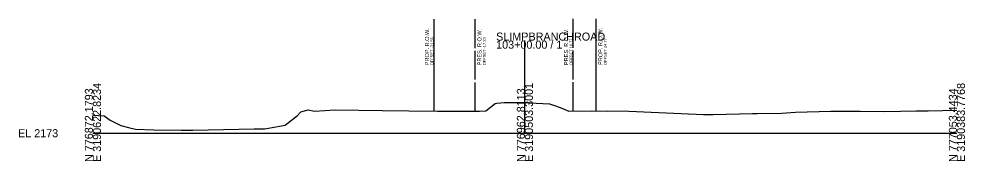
# Model space of a CAD drawing. Extents: x -26 to 303, y -10 to 13517.
# Drawn here: x -25.7 to 302.8, y -9.7 to 39.7 of the extents above; entities that cross this region are included whole.
import ezdxf

# ---------------------------------------------------------------- set-up
doc = ezdxf.new("R2010")
doc.units = 0
for name, color, linetype in [('DESIGN - ROW - Right-of-Way and Easement Labels', 7, 'Continuous'), ('DESIGN - ROW - Right-of-Way Linework', 7, 'Continuous'), ('DESIGN - SHEET - Light Grid', 7, 'Continuous'), ('SURVEY - GROUND - Top of Ground', 7, 'Continuous'), ('SURVEY - PROPERTY - ROW Lines', 7, 'Continuous'), ('SURVEY - PROPERTY - ROW Lines Text', 7, 'Continuous')]:
    doc.layers.add(name, color=color, linetype=linetype)

msp = doc.modelspace()

# ---------------------------------------------------------------- linework, layer by layer
at = {"layer": 'DESIGN - ROW - Right-of-Way Linework'}
for p, q in [((118.45, 7.63), (118.45, 39.63)), ((174.77, 7.74), (174.77, 39.74))]:
    msp.add_line(p, q, dxfattribs=at)
at = {"layer": 'DESIGN - SHEET - Light Grid'}
for p, q in [((150, 0), (150, 32.19)), ((0, 0), (150, 0)), ((150, 0), (300, 0))]:
    msp.add_line(p, q, dxfattribs=at)
at = {"layer": 'SURVEY - GROUND - Top of Ground'}
msp.add_lwpolyline([(0, 6.29), (3.95, 6.04), (5.99, 4.56), (9.72, 2.63), (12.36, 1.95), (14.77, 1.38), (21.19, 1.16), (30.66, 1.03), (31.22, 1.04), (34.66, 1.11), (55.95, 1.52), (59.69, 1.57), (61.57, 1.89), (66.72, 2.83), (67.92, 3.75), (68.99, 4.53), (70.87, 6.06), (72.22, 7.47), (74.77, 8.13), (76.91, 7.66), (84.14, 8.16), (100.42, 7.89), (109.68, 7.75), (119.63, 7.61), (123.9, 7.7), (134.27, 7.61), (136.49, 7.81), (139.66, 10.36), (140.23, 10.41), (142.81, 10.73), (143.32, 10.73), (149.93, 10.67), (151.56, 10.58), (158.49, 10.23), (160.67, 9.57), (162.81, 8.68), (165.3, 7.7), (173.22, 7.79), (178.51, 7.65), (183.5, 7.73), (211.99, 6.47), (215.34, 6.54), (229.02, 6.84), (230.66, 6.84), (239.2, 6.93), (243.9, 7.33), (256.18, 7.7), (266.4, 7.62), (275.01, 7.6), (285.86, 7.74), (290.07, 7.75), (300, 8.03)], dxfattribs=at)
at = {"layer": 'SURVEY - PROPERTY - ROW Lines'}
for p, q in [((132.77, 29.62), (132.77, 39.62)), ((166.77, 29.71), (166.77, 39.71)), ((132.77, 18.62), (132.77, 28.62)), ((166.77, 18.71), (166.77, 28.71)), ((132.77, 7.62), (132.77, 17.62)), ((166.77, 7.71), (166.77, 17.71))]:
    msp.add_line(p, q, dxfattribs=at)

# ---------------------------------------------------------------- texts
at = {"layer": 'DESIGN - ROW - Right-of-Way and Easement Labels'}
for s, height, p in [('PROP. R.O.W.', 1.4, (116.7, 23.63)), ('OFFSET -31.55', 1, (118.2, 23.63)), ('PROP. R.O.W.', 1.4, (176.92, 23.74)), ('OFFSET 24.77', 1, (178.42, 23.74))]:
    msp.add_text(s, height=height, rotation=90, dxfattribs=at).set_placement(p)
at = {"layer": 'DESIGN - SHEET - Light Grid'}
for s, p in [('SLIMPBRANCHROAD', (140, 32.19)), ('103+00.00 / 1', (140, 29.39)), ('EL 2173', (-26, -1.4))]:
    msp.add_text(s, height=2.8, dxfattribs=at).set_placement(p)
for s, p in [('E 3190622.8234', (2.8, -10)), ('E 3190503.3001', (152.8, -10)), ('E 3190383.7768', (302.8, -10)), ('N 776872.1793', (0, -10)), ('N 776962.8113', (150, -10)), ('N 777053.4434', (300, -10))]:
    msp.add_text(s, height=2.8, rotation=90, dxfattribs=at).set_placement(p)
at = {"layer": 'SURVEY - PROPERTY - ROW Lines Text'}
for s, height, p in [('PRES. R.O.W.', 1.4, (134.92, 23.62)), ('OFFSET -17.23', 1, (136.42, 23.62)), ('PRES. R.O.W.', 1.4, (165.02, 23.71)), ('OFFSET 16.77', 1, (166.52, 23.71))]:
    msp.add_text(s, height=height, rotation=90, dxfattribs=at).set_placement(p)

doc.saveas('drawing.dxf')
